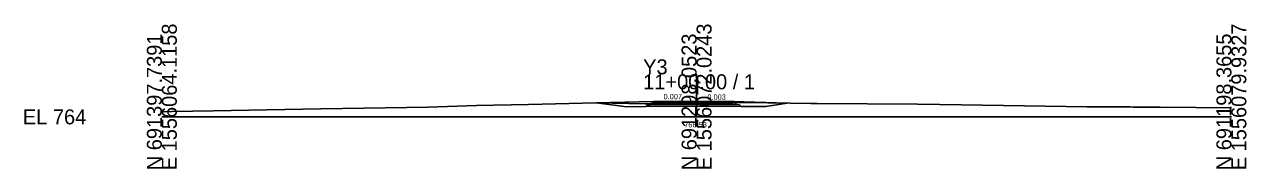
# Model space of a CAD drawing. Extents: x -26 to 203, y -10 to 1517.
# Drawn here: x -25.7 to 202.8, y 990.3 to 1017.3 of the extents above; entities that cross this region are included whole.
import ezdxf

# ---------------------------------------------------------------- set-up
doc = ezdxf.new("R2010")
doc.units = 0
for name, color, linetype in [('Exist Cross Section Cell', 7, 'Continuous'), ('Exist XS Center Line Elevation Label', 7, 'Continuous'), ('Exist XS Ground Line', 7, 'Continuous'), ('Prop CMT Pvmt Course 1', 7, 'Continuous'), ('Prop CMT Pvmt Course 2', 7, 'Continuous'), ('Prop CMT Pvmt Course 3', 7, 'Continuous'), ('Prop CMT Pvmt Surface', 7, 'Continuous'), ('Prop CMT Shld Paved Course 1', 7, 'Continuous'), ('Prop CMT Shld Paved Course 2', 7, 'Continuous'), ('Prop CMT Shld Paved Course 3', 7, 'Continuous'), ('Prop CMT Slope Grass', 7, 'Continuous'), ('Prop CMT Subgrade Earthwork', 7, 'Continuous'), ('Prop XS Earthwork Shape', 7, 'Continuous'), ('Prop XS SE Text', 7, 'Continuous')]:
    doc.layers.add(name, color=color, linetype=linetype)

msp = doc.modelspace()

# ---------------------------------------------------------------- linework, layer by layer
at = {"layer": 'Exist Cross Section Cell'}
for p, q in [((100, 1000), (100, 1007.97)), ((0, 1000), (100, 1000)), ((100, 1000), (200, 1000))]:
    msp.add_line(p, q, dxfattribs=at)
at = {"layer": 'Exist XS Ground Line'}
msp.add_lwpolyline([(0, 1000.96), (1.91, 1000.99), (9.68, 1001.13), (16.29, 1001.25), (29.73, 1001.52), (45.83, 1001.76), (49.8, 1001.83), (58.81, 1002.1), (68.57, 1002.31), (81.22, 1002.63), (90.36, 1002.44), (92.09, 1002.42), (100, 1002.53), (104, 1002.59), (106.76, 1002.61), (109.69, 1002.66), (121.39, 1002.53), (122.54, 1002.53), (141.28, 1002.37), (149.52, 1002.23), (161.34, 1002.04), (172.95, 1001.88), (181.08, 1001.85), (181.63, 1001.83), (183.02, 1001.79), (186.7, 1001.8), (200, 1001.68)], dxfattribs=at)
at = {"layer": 'Prop CMT Pvmt Course 1'}
msp.add_lwpolyline([(100, 1002.66), (100, 1002.91)], dxfattribs=at)
msp.add_lwpolyline([(100, 1002.66), (100, 1002.91)], dxfattribs=at)
at = {"layer": 'Prop CMT Pvmt Course 2'}
msp.add_lwpolyline([(100, 1002.32), (100, 1002.66)], dxfattribs=at)
msp.add_lwpolyline([(100, 1002.32), (100, 1002.66)], dxfattribs=at)
at = {"layer": 'Prop CMT Pvmt Course 3'}
msp.add_lwpolyline([(100, 1001.99), (100, 1002.32)], dxfattribs=at)
msp.add_lwpolyline([(100, 1001.99), (100, 1002.32)], dxfattribs=at)
at = {"layer": 'Prop CMT Pvmt Surface'}
for points in [[(100, 1002.91), (91.92, 1002.85)], [(100, 1002.91), (106.92, 1002.89)]]:
    msp.add_lwpolyline(points, dxfattribs=at)
at = {"layer": 'Prop CMT Shld Paved Course 1'}
for points in [[(100, 1002.91), (91.92, 1002.85), (91.67, 1002.6)], [(91.67, 1002.6), (100, 1002.66)], [(100, 1002.91), (106.92, 1002.89), (107.18, 1002.63)], [(107.18, 1002.63), (100, 1002.66)]]:
    msp.add_lwpolyline(points, dxfattribs=at)
at = {"layer": 'Prop CMT Shld Paved Course 2'}
for points in [[(100, 1002.66), (91.67, 1002.6), (91.33, 1002.26)], [(91.33, 1002.26), (100, 1002.32)], [(100, 1002.66), (107.18, 1002.63), (107.52, 1002.29)], [(107.52, 1002.29), (100, 1002.32)]]:
    msp.add_lwpolyline(points, dxfattribs=at)
at = {"layer": 'Prop CMT Shld Paved Course 3'}
for points in [[(100, 1002.32), (91.33, 1002.26), (90.84, 1002.26), (90.5, 1001.92)], [(91.47, 1001.93), (100, 1001.99)], [(100, 1002.32), (107.52, 1002.29), (108.02, 1002.28), (108.36, 1001.94)], [(108.36, 1001.94), (100, 1001.99)]]:
    msp.add_lwpolyline(points, dxfattribs=at)
at = {"layer": 'Prop CMT Slope Grass'}
for points in [[(91.92, 1002.85), (81.22, 1002.63)], [(106.92, 1002.89), (116.95, 1002.58)]]:
    msp.add_lwpolyline(points, dxfattribs=at)
at = {"layer": 'Prop CMT Subgrade Earthwork'}
for p, q in [((86.94, 1001.9), (81.22, 1002.63)), ((112.92, 1001.91), (116.95, 1002.58))]:
    msp.add_line(p, q, dxfattribs=at)
for points in [[(90.5, 1001.92), (86.94, 1001.9)], [(100, 1001.99), (90.5, 1001.92)], [(100, 1001.99), (108.36, 1001.94)], [(108.36, 1001.94), (112.92, 1001.91)]]:
    msp.add_lwpolyline(points, dxfattribs=at)
at = {"layer": 'Prop XS Earthwork Shape'}
msp.add_lwpolyline([(86.94, 1001.9), (81.22, 1002.63), (90.36, 1002.44), (92.09, 1002.42), (100, 1002.53), (104, 1002.59), (106.76, 1002.61), (109.69, 1002.66), (116.95, 1002.58), (112.92, 1001.91), (108.36, 1001.94), (100, 1001.99), (90.5, 1001.92)], close=True, dxfattribs=at)

# ---------------------------------------------------------------- texts
at = {"layer": 'Exist Cross Section Cell'}
for s, p in [('E 1556064.1158', (2.8, 990)), ('E 1556072.0243', (102.8, 990)), ('E 1556079.9327', (202.8, 990)), ('N 691397.7391', (0, 990)), ('N 691298.0523', (100, 990)), ('N 691198.3655', (200, 990))]:
    msp.add_text(s, height=2.8, rotation=90, dxfattribs=at).set_placement(p)
for s, p in [('Y3', (90, 1007.97)), ('11+00.00 / 1', (90, 1005.17)), ('EL 764', (-26, 998.6))]:
    msp.add_text(s, height=2.8, dxfattribs=at).set_placement(p)
at = {"layer": 'Exist XS Center Line Elevation Label'}
msp.add_text('766.53', height=1, dxfattribs=at).set_placement((97.69, 998.03))
at = {"layer": 'Prop XS SE Text'}
for s, rotation, p in [('0.007', 0.4011, (93.82, 1003.28)), ('0.003', 359.8281, (102.01, 1003.21))]:
    msp.add_text(s, height=1, rotation=rotation, dxfattribs=at).set_placement(p)

doc.saveas('drawing.dxf')
